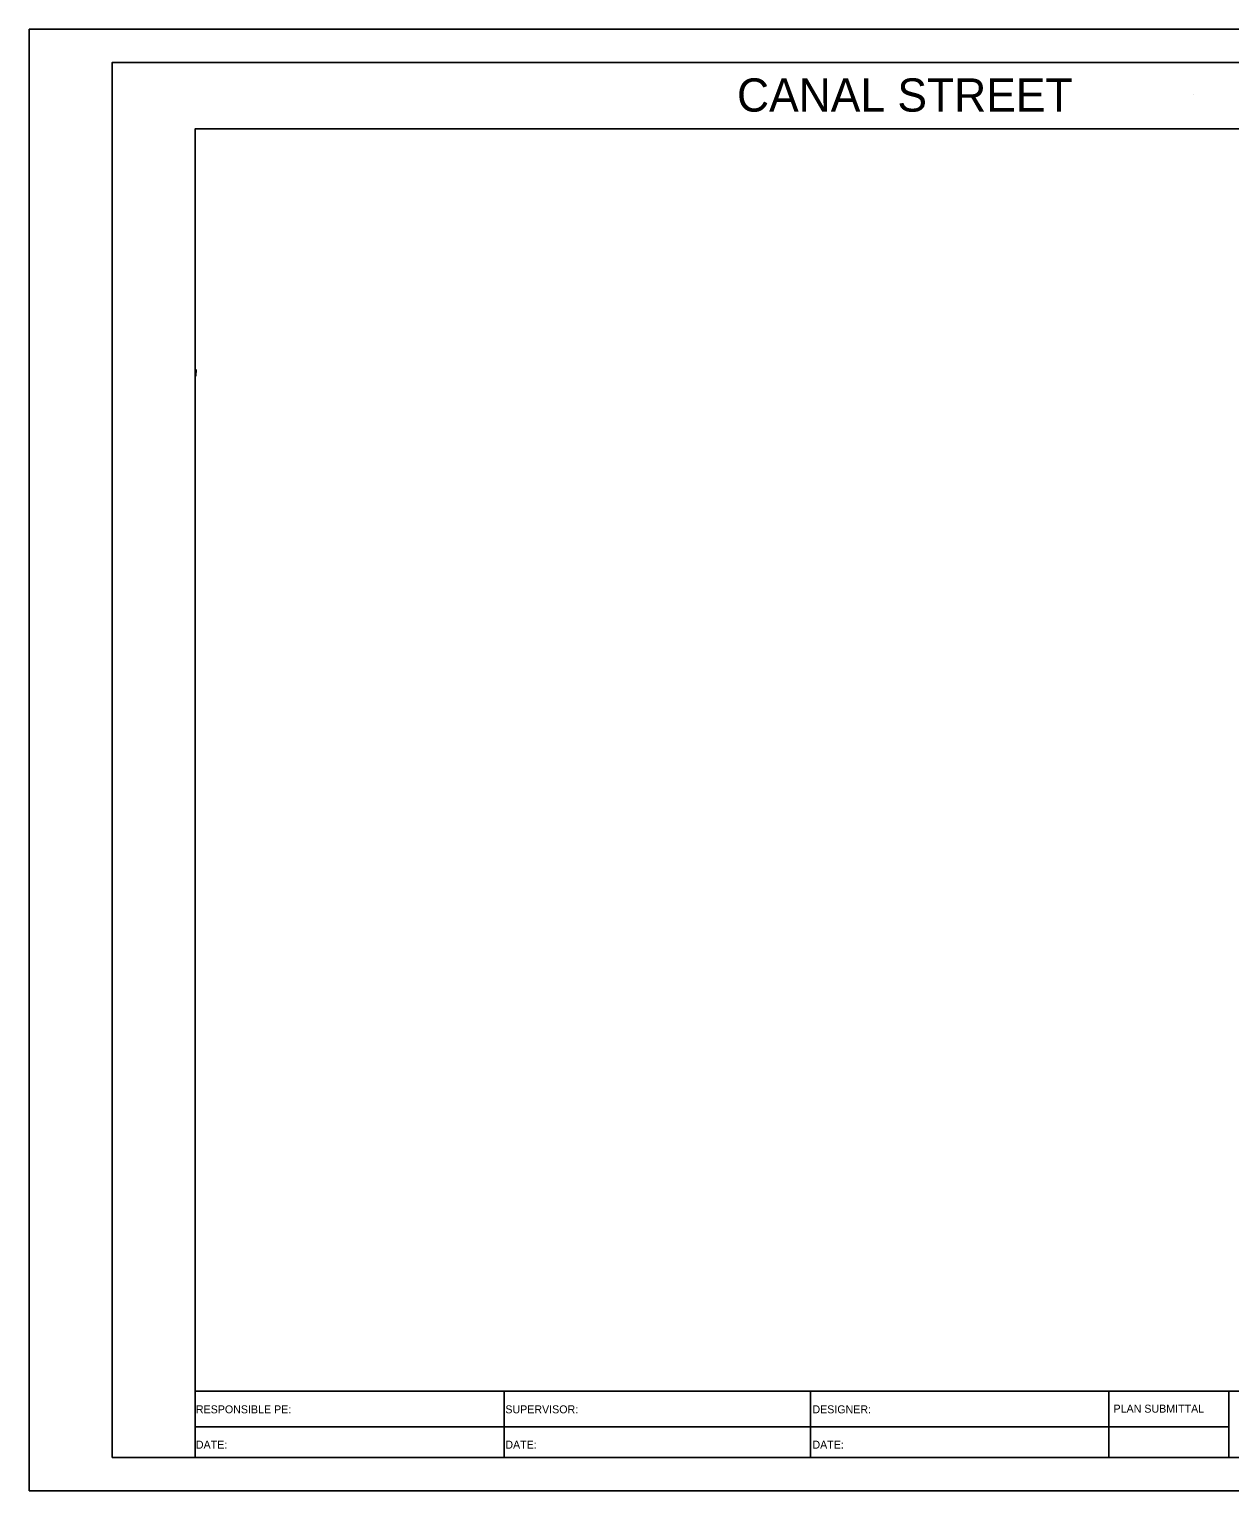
# Model space of a CAD drawing. Extents: x 1797478 to 1808916, y 246529 to 250952.
# Drawn here: x 1802116 to 1802296.8, y 250064.4 to 250284.4 of the extents above; entities that cross this region are included whole.
import ezdxf

# ---------------------------------------------------------------- set-up
doc = ezdxf.new("R2010")
doc.units = 0
for name, color, linetype in [('2', 7, 'Continuous'), ('ANNO-SHT', 7, 'Continuous'), ('ANNO-TXT', 7, 'Continuous'), ('AXIS', 7, 'Continuous'), ('DRAINAGE', 7, 'Continuous'), ('Level 1', 7, 'Continuous'), ('Level 62', 7, 'Continuous'), ('SHT-BDR', 7, 'Continuous'), ('SHT-BNDRY', 7, 'Continuous')]:
    doc.layers.add(name, color=color, linetype=linetype)

# ---------------------------------------------------------------- blocks, each defined once
blk = doc.blocks.new('SC47208')
at = {"layer": 'Level 1'}
blk.add_line((0, 0), (0, 0), dxfattribs=at)

msp = doc.modelspace()

# ---------------------------------------------------------------- linework, layer by layer
at = {"layer": '2'}
msp.add_lwpolyline([(1802141.12, 250233.21), (1802141.1, 250232.21)], dxfattribs=at)
msp.add_lwpolyline([(1802141.12, 250233.21), (1802141.1, 250232.21)], dxfattribs=at)
at = {"layer": 'AXIS'}
msp.add_line((1802141, 250189.42), (1802141, 250189.43), dxfattribs=at)
at = {"layer": 'Level 62'}
msp.add_lwpolyline([(1802116, 250064.42), (1802456, 250064.42), (1802456, 250284.42), (1802116, 250284.42)], close=True, dxfattribs=at)
at = {"layer": 'SHT-BDR'}
msp.add_lwpolyline([(1802141, 250079.43), (1802441, 250079.43), (1802441, 250269.43), (1802141, 250269.43)], close=True, dxfattribs=at)
at = {"layer": 'SHT-BNDRY'}
for p, q in [((1802141, 250069.42), (1802141, 250079.43)), ((1802187.52, 250079.43), (1802187.52, 250069.42)), ((1802233.67, 250069.42), (1802233.67, 250079.43)), ((1802278.59, 250069.42), (1802278.59, 250079.43)), ((1802296.63, 250069.42), (1802296.63, 250079.43)), ((1802141, 250074.03), (1802296.63, 250074.03))]:
    msp.add_line(p, q, dxfattribs=at)
msp.add_lwpolyline([(1802128.5, 250069.42), (1802451, 250069.42), (1802451, 250279.42), (1802128.5, 250279.42)], close=True, dxfattribs=at)

# ---------------------------------------------------------------- block references
at = {"layer": 'DRAINAGE', "xscale": 0.2, "yscale": 0.20000000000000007, "rotation": -116.41666666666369}
msp.add_blockref('SC47208', (1802291.32, 250274.62), dxfattribs=at)
msp.add_blockref('SC47208', (1802291.32, 250274.62), dxfattribs=at)

# ---------------------------------------------------------------- texts
at = {"layer": 'ANNO-SHT'}
msp.add_text('         CANAL STREET         ', height=4.9995, rotation=360, dxfattribs=at).set_placement((1802205.87, 250272.02))
at = {"layer": 'ANNO-TXT'}
for s, p in [('RESPONSIBLE PE:', (1802141.1, 250076.08)), ('SUPERVISOR:', (1802187.7, 250076.08)), ('DESIGNER:', (1802233.94, 250076.08)), ('PLAN SUBMITTAL', (1802279.28, 250076.18)), ('DATE:', (1802141.1, 250070.76)), ('DATE:', (1802187.7, 250070.76)), ('DATE:', (1802233.94, 250070.76))]:
    msp.add_text(s, height=1.2, rotation=360, dxfattribs=at).set_placement(p)

doc.saveas('drawing.dxf')
